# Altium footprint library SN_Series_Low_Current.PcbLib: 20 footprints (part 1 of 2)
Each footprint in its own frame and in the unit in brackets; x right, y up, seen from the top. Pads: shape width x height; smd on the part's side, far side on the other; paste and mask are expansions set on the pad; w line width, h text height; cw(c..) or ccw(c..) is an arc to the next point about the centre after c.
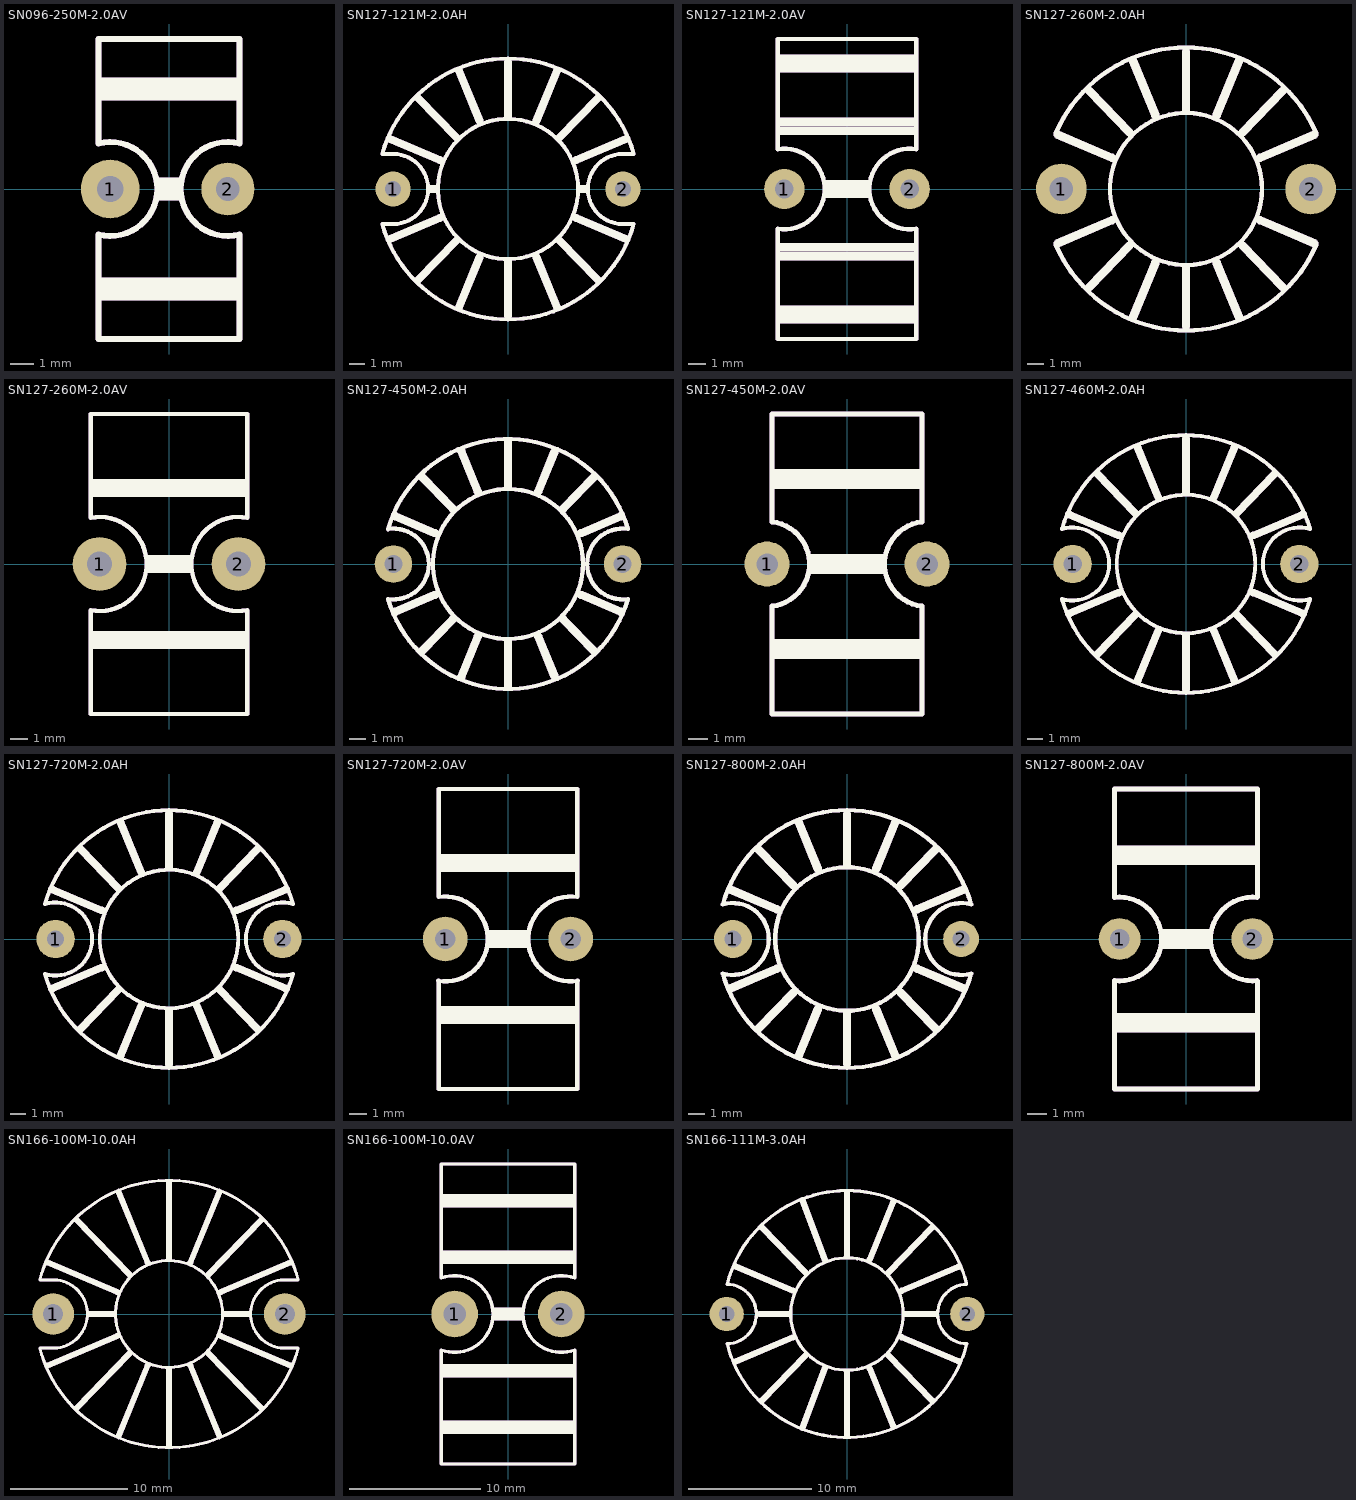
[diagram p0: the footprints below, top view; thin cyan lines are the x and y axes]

## PCBComponent_1 [mil]

## SN096-250M-2.0AV [mil]
pads (2):
  round 100 hole 45: 1(-100,0)
  round 90 hole 40: 2(100,0)
Top Overlay:
  lines w10: -120,-78 -120,-255 120,-255 120,-78 ; -120,78.09 -120,255 120,255 120,78 ; -119.87,-77.49 ccw(c-100,0) -119.85,77.5 ; 119.87,-77.49 cw(c100,0) 119.87,77.49
  lines w19.68: -115,-180 115,-180 ; -115,-160 115,-160 ; -115,160 115,160 ; -115,180 115,180 ; -15,-10 15,-10 ; -15,10 15,10
Mechanical 29:
  lines w10: -120,-78 -120,-255 120,-255 120,-78 ; -120,78.09 -120,255 120,255 120,78 ; -119.87,-77.49 ccw(c-100,0) -119.85,77.5 ; 119.87,-77.49 cw(c100,0) 119.87,77.49
  lines w19.68: -115,-180 115,-180 ; -115,-160 115,-160 ; -115,160 115,160 ; -115,180 115,180 ; -15,-10 15,-10 ; -15,10 15,10
  text "'.Designator'" at 134,61.15 h400

## SN127-121M-2.0AH [mil]
pads (2):
  round 90 hole 42: 1(-295,0) 2(295,0)
Top Overlay:
  circle w10: c0,0 r180
  lines w10: -322.77,-90 -295,-90 ccw(c-295,0) -295,90 ; -322.68,-90 ccw(c0,0) 322.77,-89.69 ; -295.96,90 -322.68,90 cw(c0,0) 322.68,90 295.96,90 ; 295,90 ccw(c295,0) 295,-90 322.77,-90
  lines w19.68: -304.21,-128.9 -175.3,-74.28 ; -304.21,128.9 -175.3,74.28 ; -229.95,-233.02 -132.5,-132.5 ; -229.95,233.02 -132.5,132.5 ; -200,0 -185,0 ; -125.55,-303.54 -72.46,-173.99 ; -125.55,303.54 -72.46,173.99 ; 0,-325 0,-185 ; 0,185 0,325 ; 72.46,-173.99 125.55,-303.54 ; 72.46,173.99 125.55,303.54 ; 132.5,-132.5 229.95,-233.02 ; 132.5,132.5 229.95,233.02 ; 175.3,-74.28 304.21,-128.9 ; 175.3,74.28 304.21,128.9 ; 185,0 200,0
Mechanical 29:
  circle w10: c0,0 r180
  lines w10: -322.77,-90 -295,-90 ccw(c-295,0) -295,90 ; -322.68,-90 ccw(c0,0) 322.77,-89.69 ; -295.96,90 -322.68,90 cw(c0,0) 322.68,90 295.96,90 ; 295,90 ccw(c295,0) 295,-90 322.77,-90
  lines w19.68: -304.21,-128.9 -175.3,-74.28 ; -304.21,128.9 -175.3,74.28 ; -229.95,-233.02 -132.5,-132.5 ; -229.95,233.02 -132.5,132.5 ; -200,0 -185,0 ; -125.55,-303.54 -72.46,-173.99 ; -125.55,303.54 -72.46,173.99 ; 0,-325 0,-185 ; 0,185 0,325 ; 72.46,-173.99 125.55,-303.54 ; 72.46,173.99 125.55,303.54 ; 132.5,-132.5 229.95,-233.02 ; 132.5,132.5 229.95,233.02 ; 175.3,-74.28 304.21,-128.9 ; 175.3,74.28 304.21,128.9 ; 185,0 200,0
  text "'.Designator'" at -290,145.15 h400

## SN127-121M-2.0AV [mil]
pads (2):
  round 90 hole 42: 1(-140,0) 2(140,0)
Top Overlay:
  lines w10: -155,-90 -155,-335 155,-335 155,-88.78 ; -155,90 -155,335 155,335 155,88.78 ; -154.8,-88.78 ccw(c-140,0) -154.8,88.78 ; 154.8,88.78 ccw(c140,0) 154.99,-88.74
  lines w19.68: -150,-290 150,-290 ; -150,-150 150,-150 ; -150,150 150,150 ; -150,290 150,290 ; -149,-270 150,-270 ; -149,-130 150,-130 ; -149,130 150,130 ; -149,270 150,270 ; -45,-10 45,-10 ; -45,10 45,10
Mechanical 29:
  lines w10: -155,-90 -155,-335 155,-335 155,-88.78 ; -155,90 -155,335 155,335 155,88.78 ; -154.8,-88.78 ccw(c-140,0) -154.8,88.78 ; 154.8,88.78 ccw(c140,0) 154.99,-88.74
  lines w19.68: -150,-290 150,-290 ; -150,-150 150,-150 ; -150,150 150,150 ; -150,290 150,290 ; -149,-270 150,-270 ; -149,-130 150,-130 ; -149,130 150,130 ; -149,270 150,270 ; -45,-10 45,-10 ; -45,10 45,10
  text "'.Designator'" at -1750,-64.85 h400

## SN127-260M-2.0AH [mil]
pads (2):
  round 120 hole 56: 1(-295,0) 2(295,0)
Top Overlay:
  circle w10: c0,0 r180
  lines w10: -308.45,-130.7 ccw(c0,0) 308.45,-130.7 ; -308.45,130.7 cw(c0,0) 308.45,130.7
  lines w19.68: -304.21,-128.9 -175.3,-74.28 ; -304.21,128.9 -175.3,74.28 ; -229.95,-233.02 -132.5,-132.5 ; -229.95,233.02 -132.5,132.5 ; -125.55,-303.54 -72.46,-173.99 ; -125.55,303.54 -72.46,173.99 ; 0,-325 0,-185 ; 0,185 0,325 ; 72.46,-173.99 125.55,-303.54 ; 72.46,173.99 125.55,303.54 ; 132.5,-132.5 229.95,-233.02 ; 132.5,132.5 229.95,233.02 ; 175.3,-74.28 304.21,-128.9 ; 175.3,74.28 304.21,128.9
Mechanical 29:
  circle w10: c0,0 r180
  lines w10: -308.45,-130.7 ccw(c0,0) 308.45,-130.7 ; -308.45,130.7 cw(c0,0) 308.45,130.7
  lines w19.68: -304.21,-128.9 -175.3,-74.28 ; -304.21,128.9 -175.3,74.28 ; -229.95,-233.02 -132.5,-132.5 ; -229.95,233.02 -132.5,132.5 ; -125.55,-303.54 -72.46,-173.99 ; -125.55,303.54 -72.46,173.99 ; 0,-325 0,-185 ; 0,185 0,325 ; 72.46,-173.99 125.55,-303.54 ; 72.46,173.99 125.55,303.54 ; 132.5,-132.5 229.95,-233.02 ; 132.5,132.5 229.95,233.02 ; 175.3,-74.28 304.21,-128.9 ; 175.3,74.28 304.21,128.9
  text "'.Designator'" at -290,145.15 h400

## SN127-260M-2.0AV [mil]
pads (2):
  round 120 hole 56: 1(-155,0) 2(155,0)
Top Overlay:
  lines w10: -175,-103.08 -175,-335 175,-335 175,-103.08 ; -174.35,-103.2 ccw(c-155,0) -175,103.08 -175,335 175,335 175,103.08 ccw(c155,0) 174.35,-103.2
  lines w19.68: -170,-180 170,-180 ; -170,-160 170,-160 ; -170,160 170,160 ; -170,180 170,180 ; -45,-10 45,-10 ; -45,10 45,10
Mechanical 29:
  lines w10: -175,-103.08 -175,-335 175,-335 175,-103.08 ; -174.35,-103.2 ccw(c-155,0) -175,103.08 -175,335 175,335 175,103.08 ccw(c155,0) 174.35,-103.2
  lines w19.68: -170,-180 170,-180 ; -170,-160 170,-160 ; -170,160 170,160 ; -170,180 170,180 ; -45,-10 45,-10 ; -45,10 45,10
  text "'.Designator'" at -1750,-64.85 h400

## SN127-450M-2.0AH [mil]
pads (2):
  round 90 hole 43: 1(-275,0) 2(275,0)
Top Overlay:
  circle w10: c0,0 r180
  lines w10: -288.16,83.46 cw(c0,0) 288,84 ccw(c275,0) 288,-84 cw(c0,0) -288,-84 ccw(c-275,0) -288,84
  lines w19.68: -270.21,-114.5 -175.3,-74.28 ; -270.21,114.5 -175.3,74.28 ; -206.36,-208.68 -132.5,-132.5 ; -206.36,208.68 -132.5,132.5 ; -112.26,-271.12 -72.46,-173.99 ; -112.26,271.12 -72.46,173.99 ; 0,-295 0,-185 ; 0,185 0,295 ; 72.46,-173.99 111.54,-269.37 ; 72.46,173.99 111.54,269.37 ; 132.5,-132.5 206.36,-208.68 ; 132.5,132.5 206.36,208.68 ; 175.3,-74.28 270.21,-114.5 ; 175.3,74.28 270.21,114.5
Mechanical 29:
  circle w10: c0,0 r180
  lines w10: -288.16,83.46 cw(c0,0) 288,84 ccw(c275,0) 288,-84 cw(c0,0) -288,-84 ccw(c-275,0) -288,84
  lines w19.68: -270.21,-114.5 -175.3,-74.28 ; -270.21,114.5 -175.3,74.28 ; -206.36,-208.68 -132.5,-132.5 ; -206.36,208.68 -132.5,132.5 ; -112.26,-271.12 -72.46,-173.99 ; -112.26,271.12 -72.46,173.99 ; 0,-295 0,-185 ; 0,185 0,295 ; 72.46,-173.99 111.54,-269.37 ; 72.46,173.99 111.54,269.37 ; 132.5,-132.5 206.36,-208.68 ; 132.5,132.5 206.36,208.68 ; 175.3,-74.28 270.21,-114.5 ; 175.3,74.28 270.21,114.5
  text "'.Designator'" at -290,145.15 h400

## SN127-450M-2.0AV [mil]
pads (2):
  round 90 hole 43: 1(-160,0) 2(160,0)
Top Overlay:
  lines w10: -150.07,-84.42 ccw(c-160,0) -149.46,84.34 ; -150,-85 -150,-300 150,-300 150,-84.34 ; -150,84.34 -150,300 150,300 150,84.34 ; 149.46,-84.34 cw(c160,0) 149.46,84.34
  lines w19.68: -145,-180 145,-180 ; -145,-160 145,-160 ; -145,160 145,160 ; -145,180 145,180 ; -70,-10 70,-10 ; -70,10 70,10
Mechanical 29:
  lines w10: -150.07,-84.42 ccw(c-160,0) -149.46,84.34 ; -150,-85 -150,-300 150,-300 150,-84.34 ; -150,84.34 -150,300 150,300 150,84.34 ; 149.46,-84.34 cw(c160,0) 149.46,84.34
  lines w19.68: -145,-180 145,-180 ; -145,-160 145,-160 ; -145,160 145,160 ; -145,180 145,180 ; -70,-10 70,-10 ; -70,10 70,10
  text "'.Designator'" at -1750,-64.85 h400

## SN127-460M-2.0AH [mil]
pads (2):
  round 100 hole 48: 1(-295,0) 2(295,0)
Top Overlay:
  circle w10: c0,0 r180
  lines w10: -322.37,-91.11 ccw(c0,0) 322.37,-91.11 ; -322.11,92.03 cw(c0,0) 322.19,91.77 ; -322.02,-91.08 ccw(c-295,0) -322.02,91.08 ; 322.02,-91.08 cw(c295,0) 322.02,91.08
  lines w19.68: -304.21,-128.9 -175.3,-74.28 ; -304.21,128.9 -175.3,74.28 ; -229.95,-233.02 -132.5,-132.5 ; -229.95,233.02 -132.5,132.5 ; -125.55,-303.54 -72.46,-173.99 ; -125.55,303.54 -72.46,173.99 ; 0,-325 0,-185 ; 0,185 0,325 ; 72.46,-173.99 125.55,-303.54 ; 72.46,173.99 125.55,303.54 ; 132.5,-132.5 229.95,-233.02 ; 132.5,132.5 229.95,233.02 ; 175.3,-74.28 304.21,-128.9 ; 175.3,74.28 304.21,128.9
Mechanical 29:
  circle w10: c0,0 r180
  lines w10: -322.37,-91.11 ccw(c0,0) 322.37,-91.11 ; -322.11,92.03 cw(c0,0) 322.19,91.77 ; -322.02,-91.08 ccw(c-295,0) -322.02,91.08 ; 322.02,-91.08 cw(c295,0) 322.02,91.08
  lines w19.68: -304.21,-128.9 -175.3,-74.28 ; -304.21,128.9 -175.3,74.28 ; -229.95,-233.02 -132.5,-132.5 ; -229.95,233.02 -132.5,132.5 ; -125.55,-303.54 -72.46,-173.99 ; -125.55,303.54 -72.46,173.99 ; 0,-325 0,-185 ; 0,185 0,325 ; 72.46,-173.99 125.55,-303.54 ; 72.46,173.99 125.55,303.54 ; 132.5,-132.5 229.95,-233.02 ; 132.5,132.5 229.95,233.02 ; 175.3,-74.28 304.21,-128.9 ; 175.3,74.28 304.21,128.9
  text "'.Designator'" at -290,145.15 h400

## SN127-720M-2.0AH [mil]
pads (2):
  round 100 hole 45: 1(-295,0) 2(295,0)
Top Overlay:
  circle w10: c0,0 r180
  lines w10: -322.42,-90.96 ccw(c-295,0) -322.42,90.96 cw(c0,0) 322.42,90.96 ccw(c295,0) 322.42,-90.96 cw(c0,0) -322.42,-90.96
  lines w19.68: -304.21,-128.9 -175.3,-74.28 ; -304.21,128.9 -175.3,74.28 ; -229.95,-233.02 -132.5,-132.5 ; -229.95,233.02 -132.5,132.5 ; -125.55,-303.54 -72.46,-173.99 ; -125.55,303.54 -72.46,173.99 ; 0,-325 0,-185 ; 0,185 0,325 ; 72.46,-173.99 125.55,-303.54 ; 72.46,173.99 125.55,303.54 ; 132.5,-132.5 229.95,-233.02 ; 132.5,132.5 229.95,233.02 ; 175.3,-74.28 304.21,-128.9 ; 175.3,74.28 304.21,128.9
Mechanical 29:
  circle w10: c0,0 r180
  lines w10: -322.42,-90.96 ccw(c-295,0) -322.42,90.96 cw(c0,0) 322.42,90.96 ccw(c295,0) 322.42,-90.96 cw(c0,0) -322.42,-90.96
  lines w19.68: -304.21,-128.9 -175.3,-74.28 ; -304.21,128.9 -175.3,74.28 ; -229.95,-233.02 -132.5,-132.5 ; -229.95,233.02 -132.5,132.5 ; -125.55,-303.54 -72.46,-173.99 ; -125.55,303.54 -72.46,173.99 ; 0,-325 0,-185 ; 0,185 0,325 ; 72.46,-173.99 125.55,-303.54 ; 72.46,173.99 125.55,303.54 ; 132.5,-132.5 229.95,-233.02 ; 132.5,132.5 229.95,233.02 ; 175.3,-74.28 304.21,-128.9 ; 175.3,74.28 304.21,128.9
  text "'.Designator'" at -290,145.15 h400

## SN127-720M-2.0AV [mil]
pads (2):
  round 100 hole 45: 1(-140,0) 2(140,0)
Top Overlay:
  lines w10: -155.29,-93.76 ccw(c-140,0) -154.82,93.84 ; -155,-93.76 -155,-335 155,-335 155,-93.76 ; -155,93.84 -155,335 155,335 155,93.84 ; 154.82,93.84 ccw(c140,0) 155.29,-93.76
  lines w19.68: -150,-180 150,-180 ; -150,-160 150,-160 ; -150,160 150,160 ; -150,180 150,180 ; -40,-10 40,-10 ; -40,10 39,10
Mechanical 29:
  lines w10: -155.29,-93.76 ccw(c-140,0) -154.82,93.84 ; -155,-93.76 -155,-335 155,-335 155,-93.76 ; -155,93.84 -155,335 155,335 155,93.84 ; 154.82,93.84 ccw(c140,0) 155.29,-93.76
  lines w19.68: -150,-180 150,-180 ; -150,-160 150,-160 ; -150,160 150,160 ; -150,180 150,180 ; -40,-10 40,-10 ; -40,10 39,10
  text "'.Designator'" at -1750,-64.85 h400

## SN127-800M-2.0AH [mil]
pads (2):
  round 90 hole 40: 1(-270,0)
  round 85 hole 40: 2(270,0)
Top Overlay:
  circle w10: c0,0 r170
  lines w10: -293.98,81.55 cw(c-270,0) -293.89,-81.57 ccw(c0,0) 293.89,-81.57 cw(c270,0) 293.89,81.57 ccw(c0,0) -293.9,81.52
  lines w19.68: -276.59,-117.2 -166.1,-70.38 ; -276.59,117.2 -166.1,70.38 ; -209.07,-211.48 -125.54,-125.32 ; -209.07,211.48 -125.54,125.32 ; -114.17,-275.78 -68.66,-164.74 ; -114.17,275.78 -68.66,164.74 ; 0,-295 0,-175 ; 0,175 0,295 ; 68.66,-164.74 114.17,-275.78 ; 68.66,164.74 114.17,275.78 ; 125.54,-125.32 209.07,-211.48 ; 125.54,125.32 209.07,211.48 ; 166.1,-70.38 276.59,-117.2 ; 166.1,70.38 276.59,117.2
Mechanical 29:
  circle w10: c0,0 r170
  lines w10: -293.98,81.55 cw(c-270,0) -293.89,-81.57 ccw(c0,0) 293.89,-81.57 cw(c270,0) 293.89,81.57 ccw(c0,0) -293.9,81.52
  lines w19.68: -276.59,-117.2 -166.1,-70.38 ; -276.59,117.2 -166.1,70.38 ; -209.07,-211.48 -125.54,-125.32 ; -209.07,211.48 -125.54,125.32 ; -114.17,-275.78 -68.66,-164.74 ; -114.17,275.78 -68.66,164.74 ; 0,-295 0,-175 ; 0,175 0,295 ; 68.66,-164.74 114.17,-275.78 ; 68.66,164.74 114.17,275.78 ; 125.54,-125.32 209.07,-211.48 ; 125.54,125.32 209.07,211.48 ; 166.1,-70.38 276.59,-117.2 ; 166.1,70.38 276.59,117.2
  text "'.Designator'" at -290,145.15 h400

## SN127-800M-2.0AV [mil]
pads (2):
  round 85 hole 40: 1(-135,0) 2(135,0)
Top Overlay:
  lines w10: -145,-84.42 -145,-305 145,-305 145,-85 ; -145,84.42 -145,305 145,305 145,85 ; -144.93,-84.42 ccw(c-135,0) -144.93,84.42 ; 144.93,-84.42 cw(c135,0) 144.93,84.42
  lines w19.68: -140,-180 140,-180 ; -140,-160 140,-160 ; -140,160 140,160 ; -140,180 140,180 ; -45,-10 45,-10 ; -45,10 45,10
Mechanical 29:
  lines w10: -145,-84.42 -145,-305 145,-305 145,-85 ; -145,84.42 -145,305 145,305 145,85 ; -144.93,-84.42 ccw(c-135,0) -144.93,84.42 ; 144.93,-84.42 cw(c135,0) 144.93,84.42
  lines w19.68: -140,-180 140,-180 ; -140,-160 140,-160 ; -140,160 140,160 ; -140,180 140,180 ; -45,-10 45,-10 ; -45,10 45,10
  text "'.Designator'" at -1750,-64.85 h400

## SN166-100M-10.0AH [mil]
pads (2):
  round 140 hole 67: 1(-390,0) 2(390,0)
Top Overlay:
  circle w10: c0,0 r180
  lines w10: -435.06,-115 ccw(c0,0) 435.06,-115 ; -435.06,115 cw(c0,0) 435.06,115 ; -434.98,-114.98 -387.8,-114.98 ; -434.98,114.98 -387.76,114.98 ; -387.7,-114.98 ccw(c-390,0) -387.66,114.98 ; 387.66,114.98 ccw(c390,0) 387.7,-114.98 ; 387.76,114.98 434.98,114.98 ; 387.8,-114.98 434.98,-114.98
  lines w19.68: -410.1,-173.77 -175.3,-74.28 ; -410.1,173.77 -175.3,74.28 ; -310,-315.59 -132.5,-132.5 ; -310,315.59 -132.5,132.5 ; -270,0 -185,0 ; -169.16,-409.95 -72.46,-173.99 ; -169.16,409.95 -72.46,173.99 ; 0,-440 0,-185 ; 0,185 0,440 ; 72.46,-173.99 169.16,-409.95 ; 72.46,173.99 169.16,409.95 ; 132.5,-132.5 310,-315.59 ; 132.5,132.5 310,315.59 ; 175.3,-74.28 410.1,-173.77 ; 175.3,74.28 410.1,173.77 ; 185,0 270,0
Mechanical 29:
  circle w10: c0,0 r180
  lines w10: -435.06,-115 ccw(c0,0) 435.06,-115 ; -435.06,115 cw(c0,0) 435.06,115 ; -434.98,-114.98 -387.8,-114.98 ; -434.98,114.98 -387.76,114.98 ; -387.7,-114.98 ccw(c-390,0) -387.66,114.98 ; 387.66,114.98 ccw(c390,0) 387.7,-114.98 ; 387.76,114.98 434.98,114.98 ; 387.8,-114.98 434.98,-114.98
  lines w19.68: -410.1,-173.77 -175.3,-74.28 ; -410.1,173.77 -175.3,74.28 ; -310,-315.59 -132.5,-132.5 ; -310,315.59 -132.5,132.5 ; -270,0 -185,0 ; -169.16,-409.95 -72.46,-173.99 ; -169.16,409.95 -72.46,173.99 ; 0,-440 0,-185 ; 0,185 0,440 ; 72.46,-173.99 169.16,-409.95 ; 72.46,173.99 169.16,409.95 ; 132.5,-132.5 310,-315.59 ; 132.5,132.5 310,315.59 ; 175.3,-74.28 410.1,-173.77 ; 175.3,74.28 410.1,173.77 ; 185,0 270,0
  text "'.Designator'" at -290,145.15 h400

## SN166-100M-10.0AV [mil]
pads (2):
  round 140 hole 67: 1(-160,0) 2(160,0)
Top Overlay:
  lines w10: -200,-108.08 -200,-450 200,-450 200,-108.08 ; -200,108.08 -200,450 200,450 200,108.08 ; -199.92,-107.85 ccw(c-160,0) -199.3,108.08 ; 199.3,108.08 ccw(c160,0) 199.92,-107.85
  lines w19.68: -195,-350 195,-350 ; -195,-330 195,-330 ; -195,-180 195,-180 ; -195,-160 195,-160 ; -195,160 195,160 ; -195,180 195,180 ; -195,330 195,330 ; -195,350 195,350 ; -40,-10 40,-10 ; -40,10 40,10
Mechanical 29:
  lines w10: -200,-108.08 -200,-450 200,-450 200,-108.08 ; -200,108.08 -200,450 200,450 200,108.08 ; -199.92,-107.85 ccw(c-160,0) -199.3,108.08 ; 199.3,108.08 ccw(c160,0) 199.92,-107.85
  lines w19.68: -195,-350 195,-350 ; -195,-330 195,-330 ; -195,-180 195,-180 ; -195,-160 195,-160 ; -195,160 195,160 ; -195,180 195,180 ; -195,330 195,330 ; -195,350 195,350 ; -40,-10 40,-10 ; -40,10 40,10
  text "'.Designator'" at -1750,-64.85 h400

## SN166-111M-3.0AH [mil]
pads (2):
  round 110 hole 50: 1(-385,0) 2(385,0)
Top Overlay:
  circle w10: c0,0 r180
  lines w10: -383.08,-96.32 ccw(c0,0) 383.08,-96.32 ; -383.1,-94.98 ccw(c-385,0) -383.07,94.98 ; -383.04,96.47 cw(c0,0) 382.76,97.57 ; 382.82,94.97 ccw(c385,0) 383.1,-94.98
  lines w19.68: -356.16,-152.26 -173.05,-74.68 ; -356.16,152.26 -173.05,74.68 ; -280,0 -185,0 ; -272.91,-277.18 -132.7,-132.43 ; -272.91,277.18 -132.7,132.43 ; -142.12,-364.21 -70.44,-171.87 ; -142.12,364.21 -70.44,171.87 ; 0,-390 0,-185 ; 0,185 0,390 ; 72.46,-173.99 148.16,-358.71 ; 72.46,173.99 148.16,358.71 ; 132.5,-132.5 272.83,-277.25 ; 132.5,132.5 272.83,277.25 ; 175.3,-74.28 356.64,-151.12 ; 175.3,74.28 356.64,151.12 ; 185,0 285,0
Mechanical 29:
  circle w10: c0,0 r180
  lines w10: -383.08,-96.32 ccw(c0,0) 383.08,-96.32 ; -383.1,-94.98 ccw(c-385,0) -383.07,94.98 ; -383.04,96.47 cw(c0,0) 382.76,97.57 ; 382.82,94.97 ccw(c385,0) 383.1,-94.98
  lines w19.68: -356.16,-152.26 -173.05,-74.68 ; -356.16,152.26 -173.05,74.68 ; -280,0 -185,0 ; -272.91,-277.18 -132.7,-132.43 ; -272.91,277.18 -132.7,132.43 ; -142.12,-364.21 -70.44,-171.87 ; -142.12,364.21 -70.44,171.87 ; 0,-390 0,-185 ; 0,185 0,390 ; 72.46,-173.99 148.16,-358.71 ; 72.46,173.99 148.16,358.71 ; 132.5,-132.5 272.83,-277.25 ; 132.5,132.5 272.83,277.25 ; 175.3,-74.28 356.64,-151.12 ; 175.3,74.28 356.64,151.12 ; 185,0 285,0
  text "'.Designator'" at -290,145.15 h400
